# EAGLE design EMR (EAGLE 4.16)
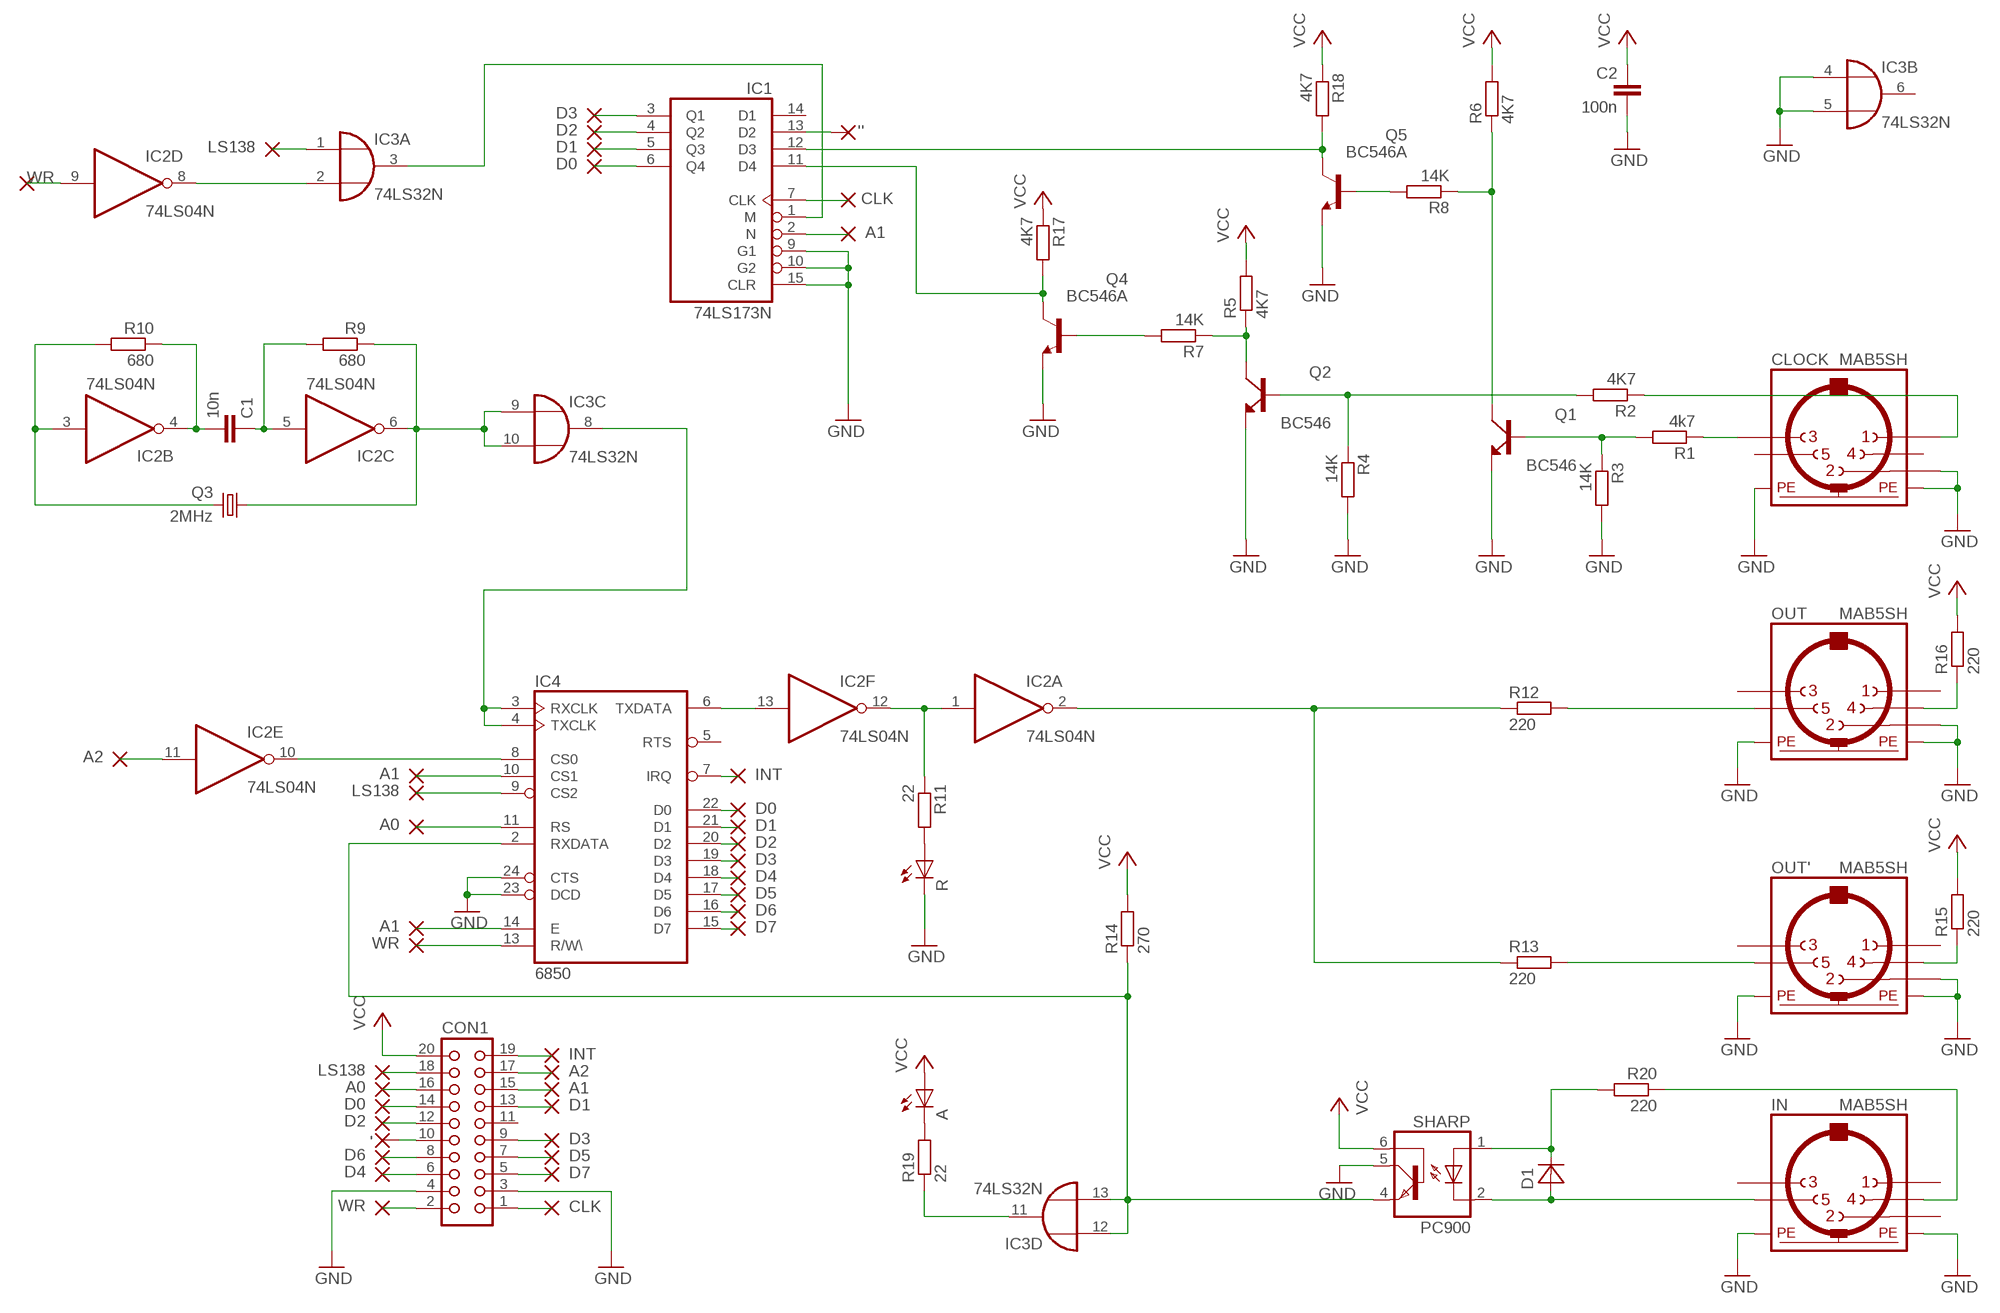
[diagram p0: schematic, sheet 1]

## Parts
'  1,27-REDONDO0.8  [1,27/0,8-REDONDO]
''  1,27-REDONDO0.8  [1,27/0,8-REDONDO]
A  LED3MM  [LED3MM]
C1  10n  C-EU075-032X103  [C075-032X103]
C2  100n  C-EU075-032X103  [C075-032X103]
CLOCK  MAB5SH  [MAB5SH]
CON1  4R20P  [4R20P]
D1  DIODE-7,5  [D-7,5]
IC1  74LS173N  [DIL16]
IC2  74LS04N  [DIL14]
IC3  74LS32N  [DIL14]
IC4  6850  [DIL24]
IN  MAB5SH  [MAB5SH]
OUT  MAB5SH  [MAB5SH]
OUT'  MAB5SH  [MAB5SH]
Q1  BC546  T-NPN-TO92-CBEA  [TO92-EBC]
Q2  BC546  T-NPN-TO92-CBEA  [TO92-EBC]
Q3  2MHz  CRYSTALHC33U-V  [HC33U-V]
Q4  BC546A  [TO92-EBC]
Q5  BC546A  [TO92-EBC]
R  LED3MM  [LED3MM]
R1  4k7  R-EU_0207/5V  [0207/5V]
R2  4K7  R-EU_0207/5V  [0207/5V]
R3  14K  R-EU_0207/5V  [0207/5V]
R4  14K  R-EU_0207/5V  [0207/5V]
R5  4K7  R-EU_0207/5V  [0207/5V]
R6  4K7  R-EU_0207/5V  [0207/5V]
R7  14K  R-EU_0207/5V  [0207/5V]
R8  14K  R-EU_0207/5V  [0207/5V]
R9  680  R-EU_0207/5V  [0207/5V]
R10  680  R-EU_0207/5V  [0207/5V]
R11  22  R-EU_0207/10  [0207/10]
R12  220  R-EU_0207/10  [0207/10]
R13  220  R-EU_0207/10  [0207/10]
R14  270  R-EU_0207/10  [0207/10]
R15  220  R-EU_0207/10  [0207/10]
R16  220  R-EU_0207/10  [0207/10]
R17  4K7  R-EU_0207/5V  [0207/5V]
R18  4K7  R-EU_0207/5V  [0207/5V]
R19  22  R-EU_0207/10  [0207/10]
R20  220  R-EU_0207/10  [0207/10]
SHARP  PC900  4N35  [DIL06]

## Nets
': '.1(P) CON1.10
A0: CON1.16 IC4.11(RS)
A1: CON1.15 IC1.2(N) IC4.10(CS1) IC4.14(E)
A2: CON1.17 IC2.11(E:I)
CLK: CON1.1 IC1.7(CLK)
D0: CON1.14 IC1.6(Q4) IC4.22(D0)
D1: CON1.13 IC1.5(Q3) IC4.21(D1)
D2: CON1.12 IC1.4(Q2) IC4.20(D2)
D3: CON1.9 IC1.3(Q1) IC4.19(D3)
D4: CON1.6 IC4.18(D4)
D5: CON1.7 IC4.17(D5)
D6: CON1.8 IC4.16(D6)
D7: CON1.5 IC4.15(D7)
GND: C2.2 CLOCK.2 CLOCK.PE CLOCK.PE@(PE) CON1.3 CON1.4 IC1.9(G1) IC1.10(G2) IC1.15(CLR) IC3.4(B:I0) IC3.5(B:I1) IC4.23(DCD) IC4.24(CTS) IN.PE IN.PE@(PE) OUT'.2 OUT'.PE OUT'.PE@(PE) OUT.2 OUT.PE OUT.PE@(PE) Q1.C(E) Q2.C(E) Q4.E Q5.E R3.2 R4.2 R.K(C) SHARP.5(COL)
INT: CON1.19 IC4.7(IRQ)
LS138: CON1.18 IC3.1(A:I0) IC4.9(CS2)
N$1: CLOCK.3 R1.1
N$2: Q1.B R1.2 R3.1
N$3: Q2.B R2.2 R4.1
N$4: Q2.E(C) R5.1 R7.1
N$5: Q1.E(C) R6.1 R8.1
N$6: CLOCK.1 R2.1
N$7: IC2.1(A:I) IC2.12(F:O) R11.1
N$8: C1.1 IC2.5(C:I) R9.2
N$9: IC2.3(B:I) Q3.2 R10.2
N$10: C1.2 IC2.4(B:O) R10.1
N$11: IC2.6(C:O) IC3.9(C:I0) IC3.10(C:I1) Q3.1 R9.1
N$12: IC3.8(C:O) IC4.3(RXCLK) IC4.4(TXCLK)
N$13: IC2.13(F:I) IC4.6(TXDATA)
N$14: IC2.2(A:O) R12.1 R13.1
N$16: IC2.8(D:O) IC3.2(A:I1)
N$18: IC2.10(E:O) IC4.8(CS0)
N$19: OUT'.5 R13.2
N$20: IC3.12(D:I0) IC3.13(D:I1) IC4.2(RXDATA) R14.1 SHARP.4(EMI)
N$21: OUT.4 R16.1
N$22: OUT'.4 R15.1
N$24: OUT.5 R12.2
N$25: IC1.1(M) IC3.3(A:O)
N$26: Q4.B R7.2
N$27: IC1.11(D4) Q4.C R17.2
N$28: IC1.12(D3) Q5.C R18.2
N$29: Q5.B R8.2
N$30: ''.1(P) IC1.13(D2)
N$33: D1.2(K) R20.2 SHARP.1(A)
N$34: IN.4 R20.1
N$35: D1.1(A) IN.5 SHARP.2(C)
N$36: A.K(C) R19.2
N$37: R11.2 R.A
N$38: IC3.11(D:O) R19.1
VCC: A.A C2.1 CON1.20 R5.2 R6.2 R14.2 R15.2 R16.2 R17.1 R18.1 SHARP.6(BAS)
WR: CON1.2 IC2.9(D:I) IC4.13(R/W\)
Unconnected: CLOCK.4 CLOCK.5 CON1.11 IC1.14(D1) IC3.6(B:O) IC4.5(RTS) IN.1 IN.2 IN.3 OUT'.1 OUT'.3 OUT.1 OUT.3

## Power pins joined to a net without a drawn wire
GND: IC1.8(GND) IC2.7(P:GND) IC3.7(P:GND) IC4.1(VSS)
VCC: IC1.16(VCC) IC2.14(P:VCC) IC3.14(P:VCC) IC4.12(VCC)

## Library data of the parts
' '' = wirepad2:1,27-REDONDO
A R = led:LED: LED
C1 C2 = rcl:C-EU: CAPACITOR, European symbol
CLOCK IN OUT OUT' = con-hirschmann:MAB5SH: Female CONNECTOR 5 pins 90 deg. with shield, horizontal (DIN 41524)
CON1 = con-harting:4R20P: CONNECTOR
D1 = discrete2:DIODE-7,5
IC1 = 74xx-eu:74*173: 4-bit D type REGISTER, 3-state
IC2 = 74xx-eu:74*04: Hex INVERTER
IC3 = 74xx-eu:74*32: Quad 2-input OR gate
IC4 = micro-motorola:6850: MICROCONTROLLER/MEMORY DEVICE
Q1 Q2 = discrete2:T-NPN-TO92-CBE
Q3 = crystal:CRYSTAL: CRYSTAL
Q4 Q5 = transistor-npn:BC546*: NPN Transistor
R1-R20 = rcl:R-EU_: RESISTOR, European symbol
SHARP = optocoupler:4N35: MOTOROLA OPTO COUPLER

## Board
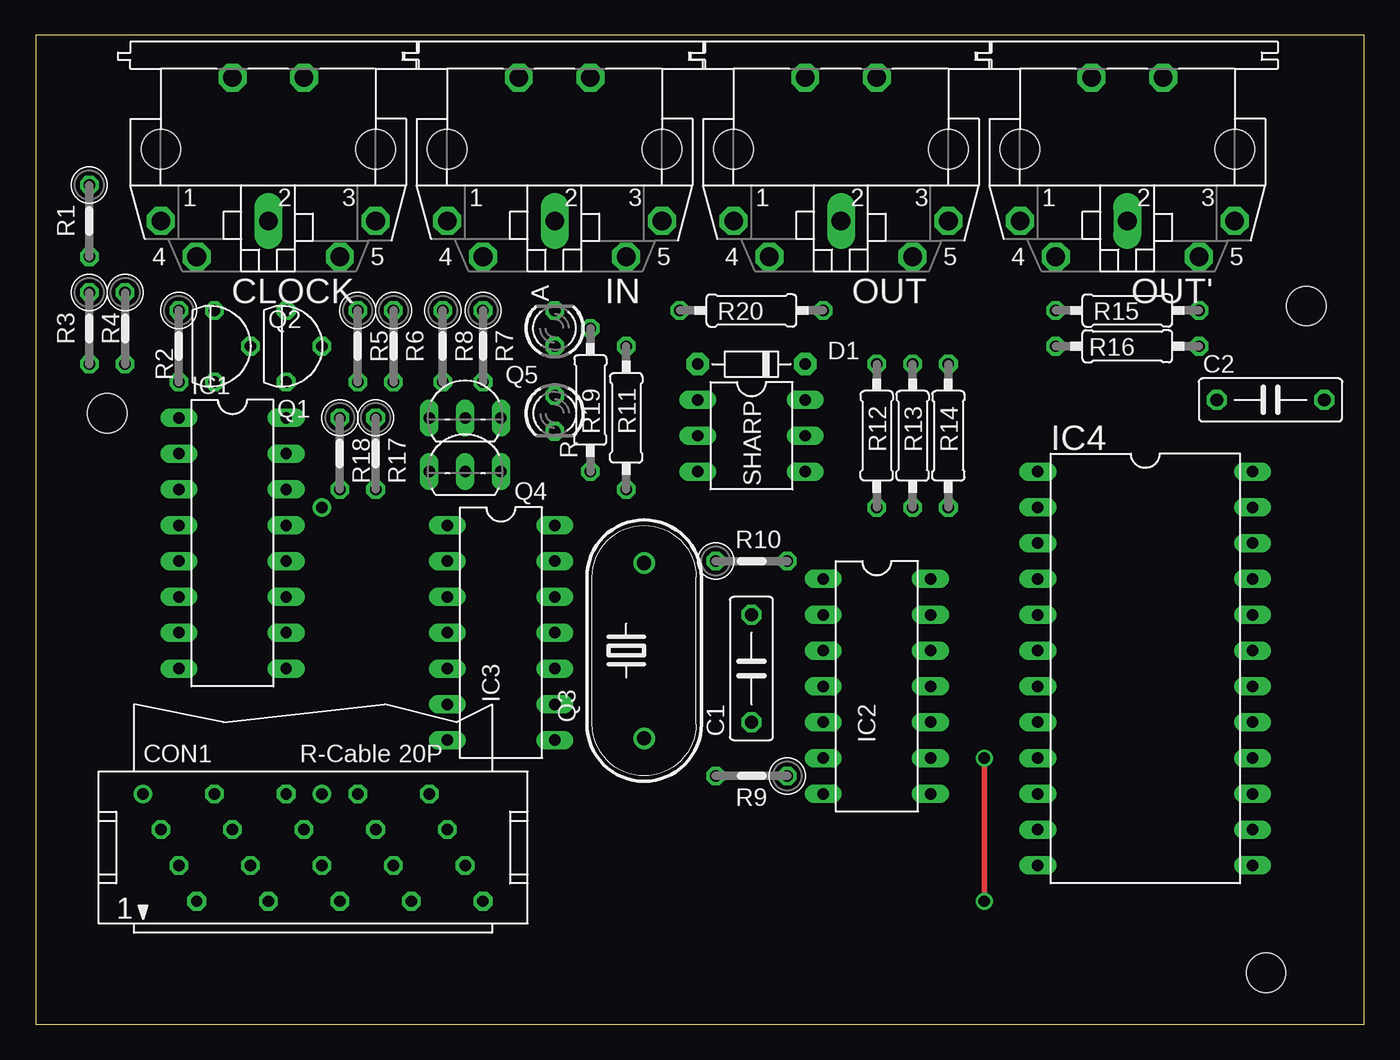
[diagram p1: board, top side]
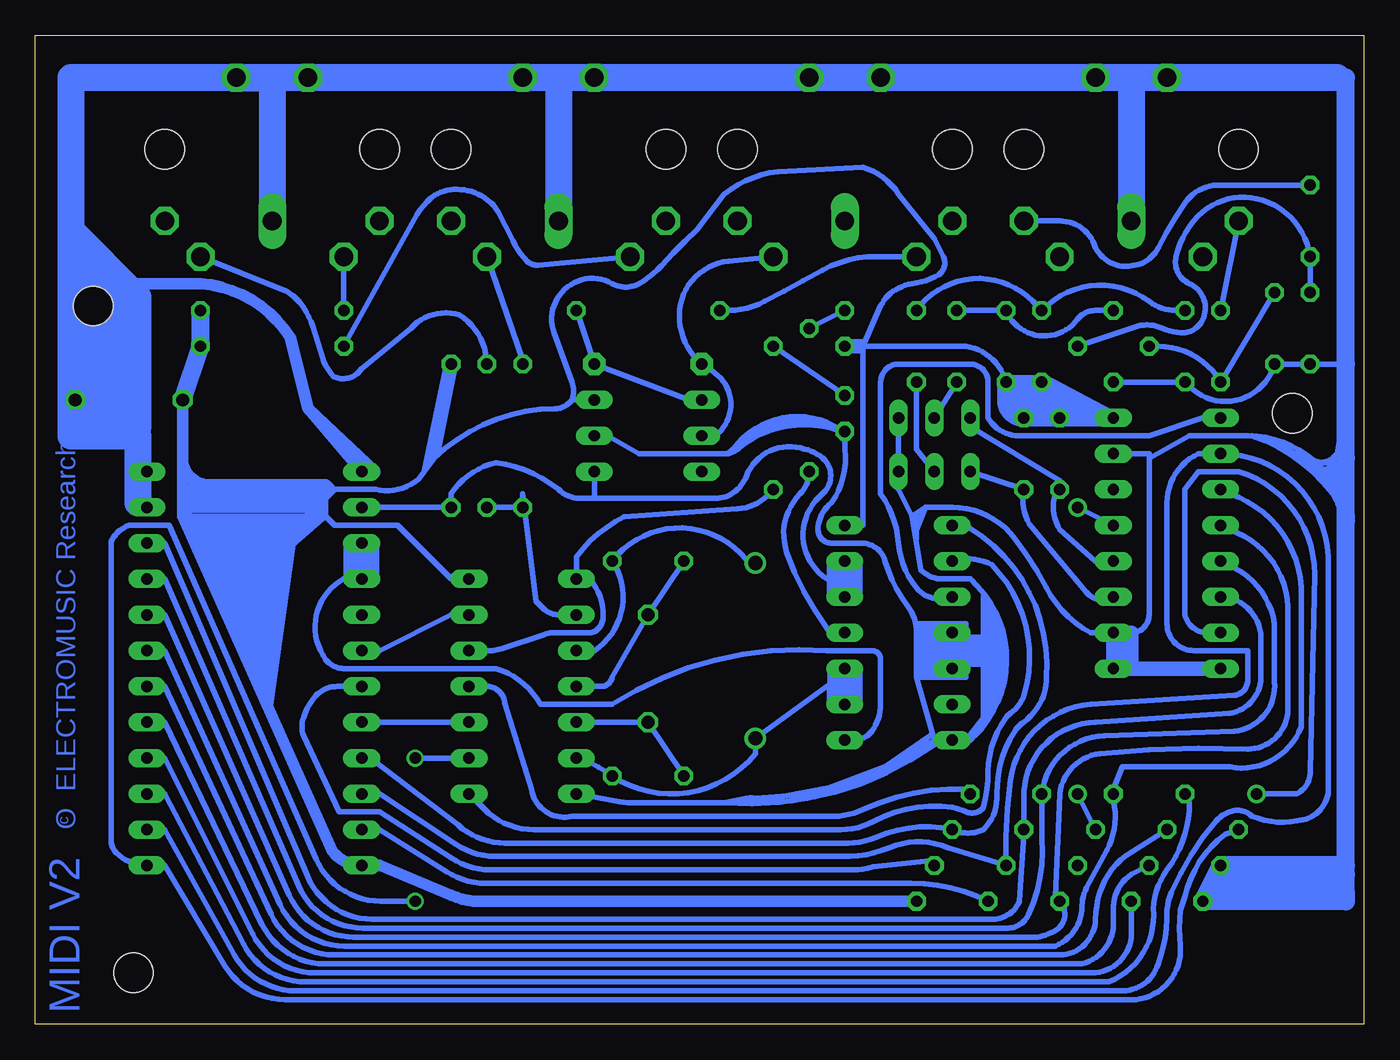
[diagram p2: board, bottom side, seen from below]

Size 94.28 x 70.15 mm. Coordinates in mm from the lower left corner, seen from the top.
Outline: 0,0 94.28,0 94.28,70.15 0,70.15 0,0
Copper layers (1*16): Top 0.035mm / dielectric 1.5mm / Bottom 0.035mm
Design rules "default": minimum track width 10mil, minimum drill 24mil, track to track 8mil, track to pad 8mil, pad to pad 8mil, via to via 8mil, smd to smd 8mil, copper to edge 40mil, drill to drill 8mil, minimum pad ring 10mil, minimum via ring 8mil, stop-mask expansion 4mil, vias tented up to drill 0mil, thermal gap 10mil
Holes 2.8 mm at 5.08,43.33 90.17,50.95 87.31,3.65

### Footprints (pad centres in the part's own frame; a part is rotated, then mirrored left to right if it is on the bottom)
1,27/0,8-REDONDO = drill 0.813 pad 1.27 round: 1 0,0
LED3MM = drill 0.813 octagon: A -1.27,0; K 1.27,0
C075-032X103 = drill 0.914 octagon: 1 -3.81,0; 2 3.81,0
MAB5SH = drill 1.321 octagon: 1 7.62,5.08; 3 -7.62,5.08; 4 5.08,7.62; 5 -5.08,7.62; PE -2.54,-5.08; PE@ 2.54,-5.08 | drill 1.321 long: 2 0,5.08 | hole 2.794: 7.62,0; -7.62,0
4R20P = drill 0.813 round: 1 -12.065,3.81 | drill 0.813 octagon: 2 -10.795,1.27; 3 -9.525,-1.27; 4 -8.255,-3.81; 5 -6.985,3.81; 6 -5.715,1.27; 7 -4.445,-1.27; 8 -3.175,-3.81; 9 -1.905,3.81; 10 -0.635,1.27; 11 0.635,-1.27; 12 1.905,-3.81; 13 3.175,3.81; 14 4.445,1.27; 15 5.715,-1.27; 16 6.985,-3.81; 17 8.255,3.81; 18 9.525,1.27; 19 10.795,-1.27; 20 12.065,-3.81
D-7,5 = drill 0.813 pad 1.6 octagon: 1 -3.81,0; 2 3.81,0
DIL16 = drill 0.813 long: 1 -8.89,-3.81; 2 -6.35,-3.81; 3 -3.81,-3.81; 4 -1.27,-3.81; 5 1.27,-3.81; 6 3.81,-3.81; 7 6.35,-3.81; 8 8.89,-3.81; 9 8.89,3.81; 10 6.35,3.81; 11 3.81,3.81; 12 1.27,3.81; 13 -1.27,3.81; 14 -3.81,3.81; 15 -6.35,3.81; 16 -8.89,3.81
DIL14 = drill 0.813 long: 1 -7.62,-3.81; 2 -5.08,-3.81; 3 -2.54,-3.81; 4 0,-3.81; 5 2.54,-3.81; 6 5.08,-3.81; 7 7.62,-3.81; 8 7.62,3.81; 9 5.08,3.81; 10 2.54,3.81; 11 0,3.81; 12 -2.54,3.81; 13 -5.08,3.81; 14 -7.62,3.81
DIL24 = drill 0.813 long: 1 -13.97,-7.62; 2 -11.43,-7.62; 3 -8.89,-7.62; 4 -6.35,-7.62; 5 -3.81,-7.62; 6 -1.27,-7.62; 7 1.27,-7.62; 8 3.81,-7.62; 9 6.35,-7.62; 10 8.89,-7.62; 11 11.43,-7.62; 12 13.97,-7.62; 13 13.97,7.62; 14 11.43,7.62; 15 8.89,7.62; 16 6.35,7.62; 17 3.81,7.62; 18 1.27,7.62; 19 -1.27,7.62; 20 -3.81,7.62; 21 -6.35,7.62; 22 -8.89,7.62; 23 -11.43,7.62; 24 -13.97,7.62
TO92-EBC = drill 0.813 octagon: B 2.54,0; C 0,-2.54; E 0,2.54
HC33U-V = drill 1.016 round: 1 -6.223,0; 2 6.223,0
TO92-EBC' = drill 0.813 long: B 0,-1.27; C -2.54,-1.27; E 2.54,-1.27
0207/5V = drill 0.813 octagon: 1 -2.54,0; 2 2.54,0
0207/10 = drill 0.813 octagon: 1 -5.08,0; 2 5.08,0
DIL06 = drill 0.813 long: 1 -2.54,-3.81; 2 0,-3.81; 3 2.54,-3.81; 4 2.54,3.81; 5 0,3.81; 6 -2.54,3.81

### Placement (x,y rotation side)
'  20.32,16.35 0 top
''  20.32,36.66 180 top
A  36.82,49.37 90 top
C1  50.79,25.23 90 top
C2  87.62,44.29 0 top
CLOCK  16.51,62.06 180 top
CON1  19.68,12.54 0 top
D1  50.79,46.83 0 top
IC1  13.96,34.12 270 top
IC2  59.68,23.96 270 top
IC3  33.02,27.78 270 top
IC4  78.73,25.23 270 top
IN  36.82,62.06 180 top
OUT  57.14,62.06 180 top
OUT'  77.47,62.06 180 top
Q1  17.78,48.09 0 top
Q2  12.69,48.09 0 top
Q3  43.17,26.51 90 top
Q4  BC546A  [TO92-EBC']  30.48,40.48 0 top
Q5  BC546A  [TO92-EBC']  30.48,44.29 0 top
R  36.82,43.33 270 top
R1  3.81,56.98 270 top
R2  10.15,48.09 270 top
R3  3.81,49.37 270 top
R4  6.34,49.37 270 top
R5  22.86,48.09 270 top
R6  25.39,48.09 270 top
R7  31.75,48.09 270 top
R8  28.89,48.09 270 top
R9  50.79,17.62 180 top
R10  50.79,32.86 0 top
R11  41.9,43.02 90 top
R12  59.68,41.74 90 top
R13  62.22,41.74 90 top
R14  64.77,41.74 90 top
R15  77.47,50.63 0 top
R16  77.47,48.09 0 top
R17  24.12,40.48 270 top
R18  21.59,40.48 270 top
R19  39.36,44.29 90 top
R20  50.79,50.63 0 top
SHARP  50.79,41.74 270 top

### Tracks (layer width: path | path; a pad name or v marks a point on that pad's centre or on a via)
'
  Bottom 0.406: CON1.10 '.1
A0
  Bottom 0.406: IC4.11 69.84,13.81 65.07,10.84 arc-34 62.3,10 32.13,10 arc26 CON1.16
A1
  Bottom 0.406: IC4.14 85.09,13.81 80.16,4.95 arc-61 75.79,2.38 17.14,2.38 arc-74 14.6,4.28 arc-18 13.96,7.46 arc28 13.65,9.36 arc18 10.47,14.44 arc25 9.52,15.08 arc65 7.93,14.76 arc-34 4.76,14.44 arc-78 2.54,16.35 2.54,33.17 arc-88 IC1.2 11.74,40.48 arc-65 13.96,36.98 13.96,28.41 arc-90 12.06,26.51 8.25,26.51 8.25,24.28 arc77 9.2,23.33 19.36,22.7 arc-78 25.08,17.3 arc-9 CON1.15 29.52,12.54 arc-45 33.65,12.54 arc19 36.46,11.9 61.6,11.9 arc35 64.47,12.8 69.84,16.35 IC4.10
A2
  Bottom 0.406: IC2.11 62.22,23.96 arc90 60.95,22.7 59.05,16.66 arc-96 56.19,14.76 37.63,14.76 arc-25 35.49,15.24 arc28 28.25,16.66 CON1.17
CLK
  Bottom 0.406: IC1.7 11.11,27.78 arc77 12.69,29.05 12.69,37.94 11.74,39.2 8.88,39.2 arc73 3.49,31.9 3.81,17.93 arc65 4.76,16.35 CON1.1
D0
  Bottom 0.406: IC4.22 85.09,34.12 74.95,10.49 arc-67 70.36,7.46 26.35,7.46 arc-67 24.44,8.73 24.12,13.49 CON1.14 24.12,16.03 arc90 19.05,21.43 9.52,22.06 arc-80 7.3,24.6 7.3,27.14 arc-83 9.84,30.32 IC1.6
D1
  Bottom 0.406: IC4.21 85.09,31.59 75.6,9.82 arc-66 71.02,6.82 25.39,6.82 arc-69 23.81,7.77 arc-29 22.86,13.17 CON1.13 arc81 18.41,20.47 9.2,20.79 arc-90 6.34,24.28 6.34,28.41 arc-58 9.52,32.54 IC1.5
D2
  Bottom 0.406: IC4.20 85.09,29.05 76.25,9.15 arc-66 71.68,6.18 23.17,6.18 arc-23 22.22,6.5 arc-119 CON1.12 21.9,9.04 21.59,16.35 arc75 18.73,19.2 arc7 8.25,19.52 arc-90 5.39,22.38 5.39,29.05 arc-74 9.52,35.08 IC1.4
D3
  Bottom 0.406: IC4.19 85.09,26.51 76.89,8.48 arc-66 72.34,5.55 21.9,5.55 arc-68 20,8.41 arc29 19.68,9.68 18.24,12.36 arc-36 17.69,15.43 17.78,16.03 CON1.9 17.78,16.66 17.14,18.25 9.52,18.25 arc-80 4.44,21.11 4.44,30.32 arc-73 9.52,37.62 IC1.3
D4
  Bottom 0.406: IC4.18 85.09,23.96 77.54,7.8 arc-65 73.01,4.92 21.59,4.92 arc-88 19.05,7.46 arc17 18.73,9.36 arc40 16.51,12.22 CON1.6
D5
  Bottom 0.406: IC4.17 85.09,21.43 78.19,7.11 arc-64 73.69,4.28 20,4.28 arc-76 17.78,7.14 17.78,8.09 arc59 16.51,10.63 CON1.7
D6
  Bottom 0.406: IC4.16 85.09,18.89 78.85,6.41 arc-63 74.38,3.65 19.05,3.65 arc-77 16.51,6.18 CON1.8
D7
  Bottom 0.406: IC4.15 85.09,16.35 79.5,5.69 arc-62 75.08,3.01 18.09,3.01 arc-69 14.92,7.77 arc40 13.96,10.95 arc-21 12.69,13.49 arc-16 12.38,15.71 CON1.5
GND
  Bottom 0.406: 15.23,40.16 12.38,41.74 8.25,41.74 arc79 1.27,36.03 1.58,36.03 1.58,35.71 | IC1.15 15.23,40.48 15.23,40.16 | 15.23,40.16 15.23,29.05 arc90 16.51,27.78 17.14,27.78 IC1.10 19.36,27.78 arc34 22.54,30.95 arc-9 24.76,34.44 arc-53 29.21,36.66 31.11,36.66 | 86.99,39.2 IC4.24 | 86.99,36.98 86.99,36.66 IC4.23 | 28.25,20.16 27.94,20.16 27.62,20.47 arc-94 27.94,31.59 29.89,31.59 arc45 31.43,32.22 32.06,36.03 | 28.25,20.16 IC3.7 30.48,20.16 | 26.98,25.87 26.98,25.55 29.21,25.55 IC3.5 | IC3.4 29.21,27.46 26.98,27.46 | 30.48,20.16 31.75,24.6 | 31.75,24.6 28.25,24.6 28.25,24.92 | 28.57,24.92 28.89,24.92 | 29.21,24.92 29.52,24.92 | 30.16,24.92 29.84,24.92 | 30.79,24.92 30.48,24.92 | 31.43,24.92 31.11,24.92 | 31.75,24.92 31.43,24.92 | 31.75,24.6 31.75,24.92 | 31.75,27.78 31.75,28.41 30.79,28.41 | 30.79,28.41 30.16,28.41 | 28.89,28.41 29.84,28.41 | 28.57,28.41 28.25,28.41 28.25,27.14 | 28.25,25.87 28.25,24.92 | 28.25,26.19 28.25,26.51 | 28.25,26.82 28.25,27.14 | 28.25,24.92 28.57,24.92 | 28.57,24.92 28.57,28.41 | 28.57,28.41 28.89,28.41 | 28.89,24.92 28.89,28.41 | 28.89,24.92 29.21,24.92 | IC3.4 29.21,24.92 | 29.52,24.92 29.52,28.09 29.21,28.09 IC3.4 | 29.52,24.92 29.84,24.92 | 29.84,28.41 29.84,24.92 | 29.84,28.41 30.16,28.41 | 30.16,28.41 30.16,24.92 | 30.48,24.92 30.16,24.92 | 30.48,24.92 30.48,28.09 30.79,28.41 | 30.79,24.92 30.79,28.41 | 31.11,24.92 30.79,24.92 | 31.11,24.92 31.11,28.09 31.43,28.09 31.43,24.92 | 26.98,27.46 26.98,30.32 | 26.98,27.14 26.98,27.46 | 26.98,25.87 26.98,26.82 | 26.98,21.74 26.98,25.87 | 26.98,21.74 26.98,21.43 26.67,21.74 26.67,30 26.35,29.36 26.35,22.38 26.03,23.01 26.03,28.73 25.71,27.46 25.71,23.96 26.98,25.87
  Bottom 0.406: 26.98,25.87 28.25,25.87 | 28.25,25.87 28.25,26.19 | 28.25,26.19 27.3,26.19 27.3,26.51 28.25,26.51 | 28.25,26.82 28.25,26.51 | 26.98,26.82 28.25,26.82 | 26.98,26.82 26.98,27.14 | 26.98,27.14 28.25,27.14 | 45.4,15.71 51.93,15.71 arc10 52.83,15.79 IC2.7 | 30.48,20.16 30.48,19.84 arc40 45.4,15.71 | Q5.E Q4.E 33.02,37.94 32.06,36.03 | 31.11,36.66 32.06,36.03 | 1.58,35.71 1.58,35.08 | 1.58,42.06 1.58,42.38 1.9,40.48 | 1.58,42.06 1.58,41.74 | 31.75,24.92 31.75,27.78 | 31.75,27.78 arc-37 32.38,29.68 arc21 33.97,32.86 arc-70 35.55,34.12 37.78,34.12 arc90 38.73,35.08 arc53 37.78,36.98 arc-41 36.82,40.79 R.K | SHARP.5 53.65,41.74 51.43,40.48 45.4,40.48 arc-37 44.45,40.79 | R.K 37.14,42.06 arc-61 44.45,40.79 | R.K 38.09,42.7 arc-76 44.76,40.79 arc8 45.08,40.48 | 91.75,41.74 C2.2 | 37.78,42.38 39.05,42.7 arc-58 44.45,40.79 | IC4.1 70.8,39.2 74.93,43.65 70.48,39.2 70.16,39.2 | 86.99,51.59 arc90 87.31,52.54 | Q1.C Q2.C 12.38,45.24 arc-119 R4.2 R3.2 1.27,46.83 | 1.9,40.48 arc71 2.54,39.84 arc47 3.81,40.16 | 1.27,40.16 arc45 1.81,40.38 1.9,40.48 | 1.27,35.71 arc-45 2.39,38.42 2.85,38.89 arc-31 7.93,41.74 arc35 2.22,37.62 | 1.58,35.71 1.58,34.76 | 1.58,35.71 arc-37 2.22,37.62 | 1.58,42.06 1.58,41.43 arc143 4.44,40.48 | 30.48,20.16 33.02,18.57 arc34 43.81,15.71 arc-5 45.4,15.71 | 45.4,15.71 43.81,16.03 arc23 43.17,16.03 | 43.17,16.03 arc-23 41.9,16.03 arc1 36.82,16.98 arc-40 30.79,20.47 33.97,18.25 39.05,16.35 43.17,16.03 | 28.25,20.16 26.98,21.74 | 31.11,36.66 31.75,35.08 | 31.75,35.08 31.75,34.44 | 31.75,35.08 31.75,36.03 | 1.58,39.84 3.17,39.2 1.58,39.52 2.54,38.89 1.9,38.89 2.22,37.94 | 2.22,37.94 1.9,37.94
  Bottom 0.406: 2.22,37.62 2.22,37.94
  Bottom 0.813: 87.31,52.54 82.55,52.54 arc53 76.2,48.73 74.93,43.65 | 74.93,43.65 IC4.1 | 74.93,43.65 70.16,39.2
  Bottom 1.016: 16.51,25.23 IC1.8 | 16.51,25.23 17.14,25.23 | 17.14,25.23 IC1.9 IC1.10 16.51,27.78 16.51,25.23 | 17.14,27.78 17.14,25.23
  Bottom 1.27: 1.9,67.14 1.27,67.14 1.27,46.83 1.27,40.16 1.27,36.03 1.27,35.71 1.27,11.27 | 1.27,9.36 1.27,8.73 CON1.4 CON1.3 1.27,11.27 | 1.27,9.36 1.27,10.63 | 1.27,10.63 1.27,11.27 | 1.27,10.63 10.15,10.63 10.15,9.36 1.27,9.36
  Bottom 1.93: 16.51,67.14 CLOCK.2 | 16.51,67.14 CLOCK.PE IN.PE@ IN.PE OUT.PE@ 57.14,67.14 | 16.51,67.14 CLOCK.PE@ 1.9,67.14 | 57.14,67.14 OUT.PE OUT'.PE@ OUT'.PE | 57.14,67.14 OUT.2 | OUT'.2 77.47,67.14 OUT'.PE | OUT'.PE 91.75,67.14 91.75,56.35 | 91.75,54.13 91.75,41.74 90.48,41.74 | 88.9,41.74 87.31,41.74 | 87.31,41.74 86.99,41.74 86.99,39.2 86.99,36.98 | 87.31,41.74 87.31,42.06 86.99,42.38 86.99,51.59 91.75,56.35 | 91.75,56.35 91.75,54.13 | 91.75,54.13 90.48,52.86 90.48,41.74 | 90.48,41.74 88.9,41.74 | 88.9,41.74 88.9,52.86
INT
  Bottom 0.406: CON1.19 30.79,11.58 34.83,11.18 arc17 36.32,10.95 61.95,10.95 arc34 64.77,11.82 69.84,15.08 72.7,15.08 75.24,20.47 arc38 75.24,21.74 arc15 74.61,23.01 arc56 72.81,23.96 IC4.7
LS138
  Bottom 0.406: IC4.9 70.48,18.89 64.29,14.15 arc-42 60.93,12.85 36.6,12.85 arc-24 34.6,13.27 arc36 CON1.18 arc-50 26.98,13.81 arc-46 26.03,16.35 arc35 24.76,20.79 arc25 24.12,21.43 arc-25 22.86,23.01 arc-28 22.54,24.6 arc-63 27.96,35.19 IC3.1
N$1
  Bottom 0.406: CLOCK.3 21.59,56.98 arc74 19.05,55.08 arc-74 16.51,53.81 arc-62 14.6,55.08 arc6 12.69,58.26 arc59 10.15,59.52 R1.1
N$2
  Bottom 0.406: R3.1 R1.2 arc-69 7.62,58.57 arc-53 11.42,57.62 arc-37 13.33,54.45 arc-78 12.38,52.54 arc91 11.42,50 arc69 13.01,49.05 arc21 14.28,49.37 arc-49 16.51,49.37 Q1.B
N$3
  Bottom 0.406: R4.1 R2.2 arc-59 14.6,48.09 Q2.B
N$4
  Bottom 0.406: Q2.E 13.33,50.63 arc37 15.23,51.27 arc-83 R5.1 23.49,51.27 arc-100 R7.1
N$5
  Bottom 0.406: Q1.E 19.05,50.63 arc-53 20.32,50 arc121 R6.1 R8.1
N$6
  Bottom 0.406: R2.1 CLOCK.1
N$7
  Bottom 0.406: IC2.12 62,26.51 arc-18 61.2,26.64 58.17,27.64 arc18 57.37,27.78 54.98,27.78 arc-45 54.34,28.04 arc-45 53.97,28.94 arc-40 54.92,31.59 IC2.1 55.88,33.17 arc26 52.49,36.01 44.44,36.56 arc-49 R11.1
N$8
  Bottom 0.406: IC2.5 C1.1 R9.2
N$9
  Bottom 0.406: Q3.2 43.49,32.54 arc-108 R10.2 arc90 54.6,26.51 IC2.3
N$10
  Bottom 0.406: R10.1 C1.2 53.34,24.6 arc58 53.97,23.96 IC2.4
N$11
  Bottom 0.406: IC2.6 arc23 R9.1 arc-85 43.17,19.2 Q3.1 38.09,23.96 37.46,23.96
  Bottom 1.27: IC3.10 36.19,25.23 36.19,22.7 IC3.9 | IC3.9 37.46,22.7 37.46,23.96 37.46,25.23 IC3.10 | IC3.9 IC3.10
N$12
  Bottom 0.406: IC3.8 36.19,20.16 arc-53 34.92,20.79 arc-37 34.28,22.7 34.28,25.87 arc-90 34.92,26.51 38.09,26.51 arc-37 53.34,22.7 58.41,22.7 arc-44 61.59,25.23 72.39,25.23 arc53 73.66,25.87 arc99 72.39,31.59 arc56 IC4.4
  Bottom 1.27: IC4.3 70.48,34.12 70.48,31.59 IC4.4 | IC4.4 71.75,31.59 71.75,34.12 IC4.3 | IC4.4 IC4.3
N$13
  Bottom 0.406: IC2.13 64.77,29.05 69.84,26.51 IC4.6
N$14
  Bottom 0.406: IC2.2 57.14,29.05 arc45 58.23,29.49 58.73,30 59.68,37.62 R12.1 R13.1
N$16
  Bottom 0.406: IC2.8 62.42,15.27 arc-45 58.88,13.81 37.12,13.81 arc-28 34.77,14.39 arc36 29.21,15.39 arc13 28.25,15.08 arc-77 26.98,15.39 arc-13 26.67,17.93 arc36 25.39,21.74 arc18 25.08,22.06 arc-18 24.44,22.7 arc-19 24.12,23.33 arc-61 26.4,32.59 arc-45 IC3.2
N$18
  Bottom 0.406: IC2.10 IC4.8
N$19
  Bottom 0.406: OUT'.5 76.71,52.11 arc23 75.8,51.51 arc28 74.56,49.45 73.89,47.27 arc-28 73.09,45.94 arc-45 71.97,45.87 arc-45 71.15,46.48 71.12,46.51 67.62,49.37 arc65 64.2,50.32 arc56 R13.2
N$20
  Bottom 0.406: IC4.2 R14.1 64.77,37.62 arc45 61.59,39.84 arc31 57.14,37.94 arc-33 55.88,37.3 54.6,37.3 | 54.6,37.3 SHARP.4 | 54.6,37.3 46.03,37.3 arc-44 44.45,37.94 arc-25 43.81,38.89 arc88 39.68,40.79 arc38 38.09,39.84 arc81 38.41,37.62 arc-108 38.09,31.59 36.82,31.59 IC3.13
  Bottom 1.27: 37.46,32.86 37.46,30.32 IC3.12 | IC3.12 36.19,30.32 36.19,32.86 IC3.13 IC3.12
N$21
  Bottom 0.406: R16.1 67.16,57.46 arc21 65.92,58.81 arc37 64.11,59.21 arc37 62.18,58.46 arc29 61.45,57.63 60.38,55.59 arc-21 59.36,54.12 arc-50 58.61,53.85 OUT.4
N$22
  Bottom 0.406: R15.1 OUT'.4
N$24
  Bottom 0.406: R12.2 59.68,47.14 OUT.5
N$25
  Bottom 0.406: IC1.1 11.42,43.02 15.23,41.74 24.44,41.74 arc59 26.67,43.02 26.67,45.55 arc-90 27.94,46.83 33.02,46.83 arc-90 34.28,45.55 34.28,37.62 arc31 33.02,34.12 arc-36 31.75,30.95 arc-73 IC3.3
N$26
  Bottom 0.406: R7.2 31.75,40.79 Q4.B
N$27
  Bottom 0.406: Q4.C R17.2 arc-40 23.74,35.45 19.68,30.63 arc-81 IC1.11
N$28
  Bottom 0.406: Q5.C 27.94,42.38 21.59,38.57 R18.2 21.9,37.62 arc-46 21.59,35.08 19.05,32.86 IC1.12
N$29
  Bottom 0.406: Q5.B R8.2
N$30
  Bottom 0.406: IC1.13 ''.1
N$33
  Bottom 0.406: R20.2 D1.2 47.94,44.29 SHARP.1
N$34
  Bottom 0.406: R20.1 45.08,50.63 arc-28 42.54,51.27 arc0 38.41,53.49 arc24 35.24,54.45 IN.4
N$35
  Bottom 0.406: IN.5 45.08,54.13 arc-84 48.57,50.32 arc-50 D1.1 arc6 46.03,46.19 arc106 46.03,41.74 SHARP.2
N$36
  Bottom 0.406: R19.2 A.K
N$37
  Bottom 0.406: R.A R11.2
N$38
  Bottom 0.406: IC3.11 37.46,27.78 arc53 38.09,28.09 arc18 40.95,33.49 arc64 40,37.62 arc-46 R19.1
VCC
  Bottom 0.406: IC2.14 64.77,31.59 68.58,35.4 73.02,35.4 73.66,36.03 | 73.66,36.03 73.66,37.3 73.02,37.94 70.12,37.94 arc-53 67.08,38.66 66.67,39.2 | 66.67,39.2 65.97,40.14 | 65.97,40.14 arc44 57.39,43.66 arc-54 56.19,44.29 | 65.97,40.14 66.04,40.16 R14.2 65.08,46.83 | 65.08,46.83 66.35,39.84 66.67,39.2 | 66.67,39.2 65.08,46.83 | 65.08,46.83 64.45,46.83 65.72,40.48 | 83.5,36.03 73.97,36.03 73.66,36.03 | 56.19,44.29 SHARP.6 | IC3.14 35.55,35.4 35.55,47.78 | 35.55,48.09 35.55,47.78 | 35.55,48.09 28.25,48.09 arc67 R6.2 | 35.55,48.09 A.A | 35.55,48.09 34.28,50.95 arc37 33.02,52.22 arc16 32.06,52.54 arc-26 30.16,53.18 arc-80 29.84,54.45 30.48,55.72 33.02,58.89 arc-41 35.55,60.8 41.59,60.48 arc-32 45.4,58.89 47.3,56.35 arc-6 49.84,53.81 arc19 51.43,52.54 arc59 53.34,52.54 arc-139 57.46,49.05 56.19,45.55 arc40 56.19,44.29 | A.A 36.82,48.41 35.55,48.41 35.55,47.78 | 35.55,47.78 36.82,47.78 A.A
  Bottom 0.813: 69.84,11.27 IC4.12 | 69.84,11.27 64.78,9.16 arc-24 62.75,8.73 CON1.20 | 69.84,11.27 arc66 73.22,12.3 83.81,36.03 | 83.81,36.03 83.5,36.03 | 83.81,36.03 83.81,36.66 | 83.81,37.3 83.81,37.94 | 83.81,39.84 C2.1 | 77.78,22.7 76.2,34.12 73.97,36.03 73.97,37.62 73.66,37.94 73.34,37.94 73.66,38.25 81.91,38.25 arc80 83.81,39.84 | 83.81,37.94 83.81,39.84 | 83.81,37.94 74.29,37.94 74.29,37.3 83.81,37.3 | 83.81,36.66 83.81,37.3 | 83.81,36.66 74.29,36.66 74.29,36.35 75.24,35.71 83.18,35.71 82.86,35.08 75.56,35.08 76.51,34.44 82.55,34.44 82.23,33.81 76.51,33.81 76.83,33.17 82.23,33.17 81.91,32.54 76.83,32.54 76.83,31.9 81.59,31.9 81.28,31.27 77.15,31.27 77.15,30.63 80.96,30.63 80.64,30 77.15,30 77.15,29.36 80.32,29.36 80.01,28.73 77.47,28.73 77.47,28.09 79.69,28.09 79.69,27.46 77.78,27.46 77.78,26.82 79.37,26.82 79.05,26.19 77.78,26.19 77.78,25.55 78.73,25.55 78.42,24.92 77.78,25.23 78.1,24.28
  Bottom 1.016: 25.39,45.24 25.39,44.92 | R6.2 R5.2
  Bottom 1.27: R15.2 R16.2 C2.1 | 18.09,43.02 IC1.16 | 18.09,43.02 R18.1 R17.1 arc90 25.39,44.29 25.39,45.24 R6.2 | 18.09,43.02 R5.2 22.86,44.92 25.08,44.92 25.08,43.97 20.32,43.97
WR  (via drill 0.8)
  Top 0.406: v67.31,8.73 v67.31,18.89
  Bottom 0.406: v67.31,8.73 69.76,8.73 arc66 74.34,11.71 84.77,35.4 87.62,35.4 arc-45 88.9,34.23 88.9,13.06 arc-45 88.52,12.16 arc-45 IC4.13 85.09,11.27 80.83,4.17 arc-59 76.54,1.74 16.19,1.74 arc-87 13.01,5.55 arc14 13.01,8.09 arc9 12.69,9.04 arc41 9.84,13.49 CON1.2 | v67.31,18.89 IC2.9

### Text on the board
Bottom: c | O ELECTROMUSIC Research | MIDI V2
